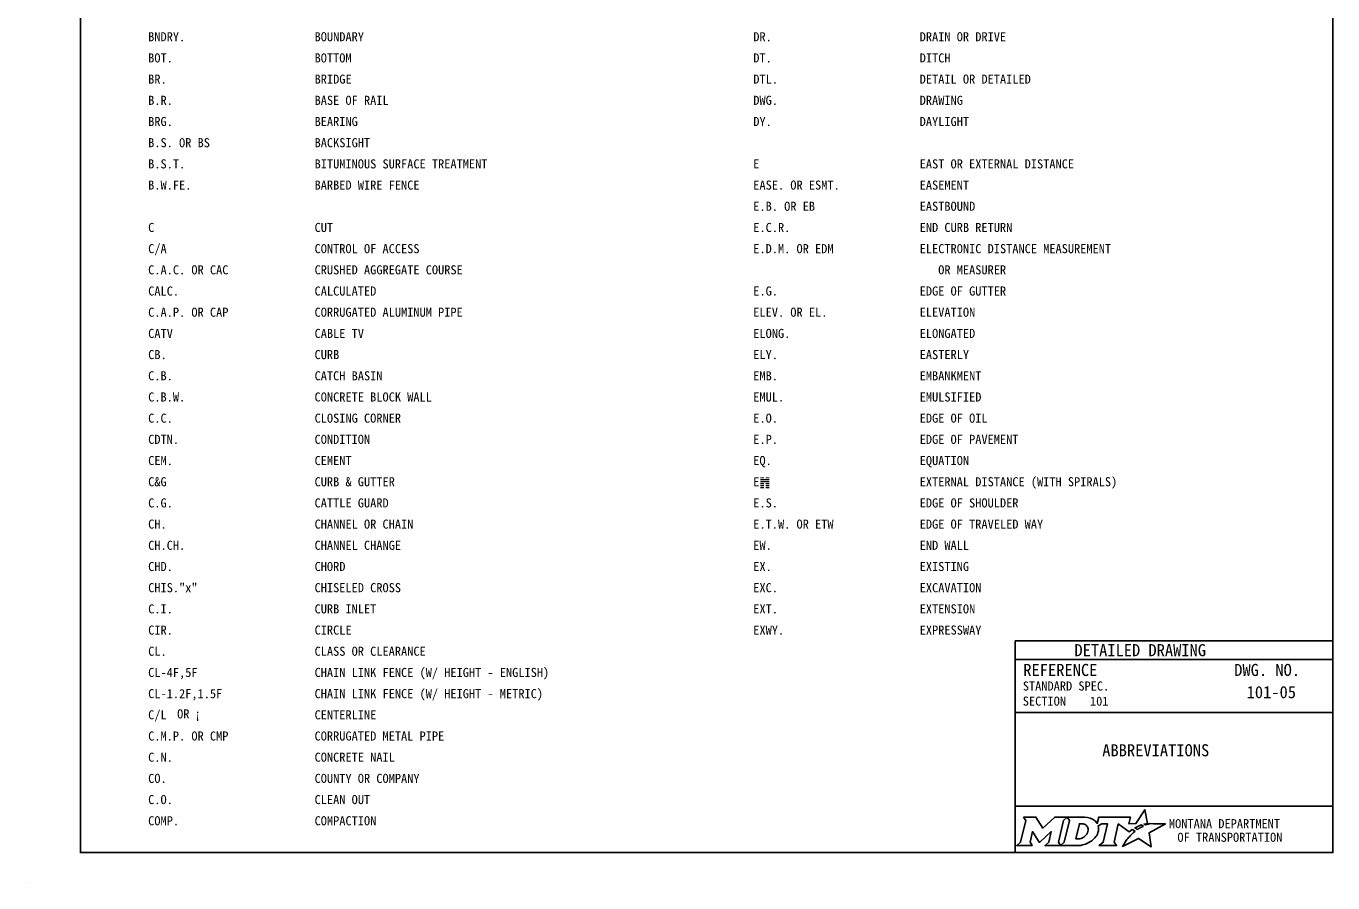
# Model space of a CAD drawing. Extents: x 49991.4 to 50021, y 49987.6 to 50011.4.
# Drawn here: x 49999.98 to 50008.61, y 49999.86 to 50005.52 of the extents above; entities that cross this region are included whole.
import ezdxf

# ---------------------------------------------------------------- set-up
doc = ezdxf.new("R2010")
doc.units = 0
for name, color, linetype in [('Default', 7, 'Continuous'), ('Level 1', 7, 'Continuous'), ('Level 2', 7, 'Continuous'), ('Level 5', 7, 'Continuous')]:
    doc.layers.add(name, color=color, linetype=linetype)

msp = doc.modelspace()

# ---------------------------------------------------------------- linework, layer by layer
at = {"layer": 'Level 1'}
msp.add_line((49999.9766, 49999.8624), (49999.9766, 49999.8624), dxfattribs=at)
msp.add_lwpolyline([(50008.6146, 50011.2628), (50000.3356, 50011.2628), (50000.3356, 50000.0624), (50008.6146, 50000.0624)], close=True, dxfattribs=at)
at = {"layer": 'Level 2'}
for p, q in [((50008.6146, 50001.4624), (50006.5146, 50001.4624)), ((50006.5146, 50001.4624), (50006.5146, 50000.0624)), ((50008.6146, 50001.3374), (50006.5146, 50001.3374)), ((50008.2507, 50001.1223), (50008.2507, 50001.1223)), ((50008.6146, 50000.9874), (50006.5146, 50000.9874)), ((50007.0089, 50001.0629), (50007.0089, 50001.0629)), ((50007.5646, 50000.7383), (50007.5646, 50000.7383)), ((50008.6146, 50000.3693), (50006.5146, 50000.3693))]:
    msp.add_line(p, q, dxfattribs=at)
for points in [[(50006.5701, 50000.2974), (50006.5842, 50000.274), (50006.5507, 50000.1307), (50006.525, 50000.1082), (50006.6266, 50000.1082), (50006.6131, 50000.131), (50006.6293, 50000.2011), (50006.673, 50000.1321), (50006.6783, 50000.1321), (50006.7534, 50000.2016), (50006.737, 50000.1305), (50006.7123, 50000.1085), (50006.8139, 50000.1085), (50006.8001, 50000.1318), (50006.8333, 50000.2742)], [(50006.8333, 50000.2742), (50006.8586, 50000.2974), (50006.7762, 50000.2974), (50006.6966, 50000.2244), (50006.6521, 50000.2971), (50006.5701, 50000.2974)], [(50006.9722, 50000.2974), (50006.8586, 50000.2974), (50006.8733, 50000.2745), (50006.8394, 50000.1307), (50006.8139, 50000.1085), (50006.9245, 50000.1085)], [(50007.3771, 50000.2447), (50007.3668, 50000.2503), (50007.3784, 50000.2531), (50007.39, 50000.2551), (50007.3726, 50000.3452), (50007.3131, 50000.2539), (50007.2658, 50000.2532), (50007.2761, 50000.2973), (50007.0669, 50000.2974), (50007.0568, 50000.2549), (50007.051, 50000.2632)], [(50006.9962, 50000.2107), (50006.995, 50000.2026), (50006.9918, 50000.1933), (50006.9876, 50000.1851), (50006.982, 50000.1776), (50006.9755, 50000.1707), (50006.9676, 50000.1644), (50006.9593, 50000.1597), (50006.9502, 50000.1558), (50006.9411, 50000.1535), (50006.9319, 50000.1526), (50006.916, 50000.1526), (50006.9396, 50000.2526), (50006.9556, 50000.2526), (50006.9632, 50000.252), (50006.9708, 50000.2501), (50006.9774, 50000.2471), (50006.9835, 50000.2429), (50006.9883, 50000.2379), (50006.992, 50000.2319), (50006.9947, 50000.2257), (50006.9963, 50000.2183), (50006.9963, 50000.2153), (50006.9962, 50000.2107)], [(50007.0636, 50000.2383), (50007.0882, 50000.2514), (50007.1251, 50000.2514), (50007.0965, 50000.1309), (50007.069, 50000.1082), (50007.1852, 50000.1082), (50007.1682, 50000.1311), (50007.1964, 50000.2513), (50007.2677, 50000.1996), (50007.2888, 50000.2147), (50007.3085, 50000.2038)], [(50007.2527, 50000.1479), (50007.2374, 50000.1235), (50007.2327, 50000.116), (50007.2269, 50000.1074), (50007.2246, 50000.1031), (50007.3299, 50000.1562), (50007.4138, 50000.1011), (50007.4007, 50000.1938), (50007.5076, 50000.2522), (50007.4583, 50000.253), (50007.4282, 50000.2534), (50007.4074, 50000.2537), (50007.4006, 50000.2522), (50007.3957, 50000.251), (50007.3873, 50000.2487), (50007.3771, 50000.2447)], [(50007.3267, 50000.2171), (50007.3243, 50000.2154), (50007.306, 50000.225), (50007.3163, 50000.2307), (50007.3204, 50000.2329), (50007.329, 50000.2369), (50007.3347, 50000.2395), (50007.3426, 50000.2425), (50007.3499, 50000.2452), (50007.3617, 50000.2378), (50007.3577, 50000.2357), (50007.3531, 50000.2332), (50007.3489, 50000.231), (50007.3439, 50000.2281), (50007.342, 50000.227), (50007.3393, 50000.2254), (50007.3368, 50000.224), (50007.3345, 50000.2224), (50007.3319, 50000.2206), (50007.3292, 50000.2188), (50007.3267, 50000.2171)], [(50006.9702, 50000.1158), (50006.9786, 50000.1184), (50006.9916, 50000.1238), (50007.012, 50000.1348)], [(50007.2666, 50000.164), (50007.2666, 50000.164)]]:
    msp.add_lwpolyline(points, dxfattribs=at)
for centre, radius, start, end in [((50006.9953, 50000.219), 0.0709, 339.53292, 15.85821), ((50006.9513, 50000.2363), 0.1183, 300.91025, 339.13831)]:
    msp.add_arc(centre, radius, start, end, dxfattribs=at)
for centre, major_axis, ratio, start_param, end_param in [((50006.9701, 50000.25), (0.0834, -0.0037), 0.568097, 0.61298, 1.570796), ((50007.0257, 50000.2573), (0.0361, -0.0295), 0.469099, 1.225588, 1.570796), ((50007.2974, 50000.1941), (-0.0112, -0.0097), 0.021651, 3.157348, 6.283185), ((50006.9248, 50000.2568), (0, 0.1484), 0.987302, 3.139398, 3.456847), ((50007.2597, 50000.1559), (-0.00694, -0.00806), 0.008222, 0, 3.137361), ((50007.2764, 50000.1742), (-0.0098, -0.0102), 0.016458, 3.141593, 6.279097)]:
    msp.add_ellipse(centre, major_axis=major_axis, ratio=ratio, start_param=start_param, end_param=end_param, dxfattribs=at)

# ---------------------------------------------------------------- texts
at = {"layer": 'Default'}
msp.add_text('OR ¡', height=0.06, dxfattribs=at).set_placement((50000.9747, 50000.9487))
at = {"layer": 'Level 2'}
for s, height, p in [('BNDRY.         ', 0.06, (50000.7833, 50005.4226)), ('BOUNDARY                                ', 0.06, (50001.8833, 50005.4226)), ('DR.            ', 0.06, (50004.7833, 50005.4226)), ('DRAIN OR DRIVE                          ', 0.06, (50005.8833, 50005.4226)), ('BOT.           ', 0.06, (50000.7833, 50005.2826)), ('BOTTOM                                  ', 0.06, (50001.8833, 50005.2826)), ('DT.            ', 0.06, (50004.7833, 50005.2826)), ('DITCH                                   ', 0.06, (50005.8833, 50005.2826)), ('BR.            ', 0.06, (50000.7833, 50005.1426)), ('BRIDGE                                  ', 0.06, (50001.8833, 50005.1426)), ('DTL.           ', 0.06, (50004.7833, 50005.1426)), ('DETAIL OR DETAILED                      ', 0.06, (50005.8833, 50005.1426)), ('B.R.           ', 0.06, (50000.7833, 50005.0026)), ('BASE OF RAIL                            ', 0.06, (50001.8833, 50005.0026)), ('DWG.           ', 0.06, (50004.7833, 50005.0026)), ('DRAWING                                 ', 0.06, (50005.8833, 50005.0026)), ('BRG.           ', 0.06, (50000.7833, 50004.8626)), ('BEARING                                 ', 0.06, (50001.8833, 50004.8626)), ('DY.            ', 0.06, (50004.7833, 50004.8626)), ('DAYLIGHT                                ', 0.06, (50005.8833, 50004.8626)), ('B.S. OR BS     ', 0.06, (50000.7833, 50004.7226)), ('BACKSIGHT                               ', 0.06, (50001.8833, 50004.7226)), ('B.S.T.         ', 0.06, (50000.7833, 50004.5826)), ('BITUMINOUS SURFACE TREATMENT            ', 0.06, (50001.8833, 50004.5826)), ('E              ', 0.06, (50004.7833, 50004.5826)), ('EAST OR EXTERNAL DISTANCE               ', 0.06, (50005.8833, 50004.5826)), ('B.W.FE.        ', 0.06, (50000.7833, 50004.4426)), ('BARBED WIRE FENCE                       ', 0.06, (50001.8833, 50004.4426)), ('EASE. OR ESMT. ', 0.06, (50004.7833, 50004.4426)), ('EASEMENT                                ', 0.06, (50005.8833, 50004.4426)), ('E.B. OR EB     ', 0.06, (50004.7833, 50004.3026)), ('EASTBOUND                               ', 0.06, (50005.8833, 50004.3026)), ('C              ', 0.06, (50000.7833, 50004.1626)), ('CUT                                     ', 0.06, (50001.8833, 50004.1626)), ('E.C.R.         ', 0.06, (50004.7833, 50004.1626)), ('END CURB RETURN                         ', 0.06, (50005.8833, 50004.1626)), ('C/A            ', 0.06, (50000.7833, 50004.0226)), ('CONTROL OF ACCESS                       ', 0.06, (50001.8833, 50004.0226)), ('E.D.M. OR EDM  ', 0.06, (50004.7833, 50004.0226)), ('ELECTRONIC DISTANCE MEASUREMENT         ', 0.06, (50005.8833, 50004.0226)), ('C.A.C. OR CAC  ', 0.06, (50000.7833, 50003.8826)), ('CRUSHED AGGREGATE COURSE                ', 0.06, (50001.8833, 50003.8826)), ('   OR MEASURER                          ', 0.06, (50005.8833, 50003.8826)), ('CALC.          ', 0.06, (50000.7833, 50003.7426)), ('CALCULATED                              ', 0.06, (50001.8833, 50003.7426)), ('E.G.           ', 0.06, (50004.7833, 50003.7426)), ('EDGE OF GUTTER                          ', 0.06, (50005.8833, 50003.7426)), ('C.A.P. OR CAP  ', 0.06, (50000.7833, 50003.6026)), ('CORRUGATED ALUMINUM PIPE                ', 0.06, (50001.8833, 50003.6026)), ('ELEV. OR EL.   ', 0.06, (50004.7833, 50003.6026)), ('ELEVATION                               ', 0.06, (50005.8833, 50003.6026)), ('CATV           ', 0.06, (50000.7833, 50003.4626)), ('CABLE TV                                ', 0.06, (50001.8833, 50003.4626)), ('ELONG.         ', 0.06, (50004.7833, 50003.4626)), ('ELONGATED                               ', 0.06, (50005.8833, 50003.4626)), ('CB.            ', 0.06, (50000.7833, 50003.3226)), ('CURB                                    ', 0.06, (50001.8833, 50003.3226)), ('ELY.           ', 0.06, (50004.7833, 50003.3226)), ('EASTERLY                                ', 0.06, (50005.8833, 50003.3226)), ('C.B.           ', 0.06, (50000.7833, 50003.1826)), ('CATCH BASIN                             ', 0.06, (50001.8833, 50003.1826)), ('EMB.           ', 0.06, (50004.7833, 50003.1826)), ('EMBANKMENT                              ', 0.06, (50005.8833, 50003.1826)), ('C.B.W.         ', 0.06, (50000.7833, 50003.0426)), ('CONCRETE BLOCK WALL                     ', 0.06, (50001.8833, 50003.0426)), ('EMUL.          ', 0.06, (50004.7833, 50003.0426)), ('EMULSIFIED                              ', 0.06, (50005.8833, 50003.0426)), ('C.C.           ', 0.06, (50000.7833, 50002.9026)), ('CLOSING CORNER                          ', 0.06, (50001.8833, 50002.9026)), ('E.O.           ', 0.06, (50004.7833, 50002.9026)), ('EDGE OF OIL                             ', 0.06, (50005.8833, 50002.9026)), ('CDTN.          ', 0.06, (50000.7833, 50002.7626)), ('CONDITION                               ', 0.06, (50001.8833, 50002.7626)), ('E.P.           ', 0.06, (50004.7833, 50002.7626)), ('EDGE OF PAVEMENT                        ', 0.06, (50005.8833, 50002.7626)), ('CEM.           ', 0.06, (50000.7833, 50002.6226)), ('CEMENT                                  ', 0.06, (50001.8833, 50002.6226)), ('EQ.            ', 0.06, (50004.7833, 50002.6226)), ('EQUATION                                ', 0.06, (50005.8833, 50002.6226)), ('C&G            ', 0.06, (50000.7833, 50002.4826)), ('CURB & GUTTER                           ', 0.06, (50001.8833, 50002.4826)), ('E䷬', 0.06, (50004.7833, 50002.4826)), ('EXTERNAL DISTANCE (WITH SPIRALS)        ', 0.06, (50005.8833, 50002.4826)), ('C.G.            ', 0.06, (50000.7833, 50002.3426)), ('CATTLE GUARD                        ', 0.06, (50001.8833, 50002.3426)), ('E.S.           ', 0.06, (50004.7833, 50002.3426)), ('EDGE OF SHOULDER                        ', 0.06, (50005.8833, 50002.3426)), ('CH.            ', 0.06, (50000.7833, 50002.2026)), ('CHANNEL OR CHAIN                        ', 0.06, (50001.8833, 50002.2026)), ('E.T.W. OR ETW  ', 0.06, (50004.7833, 50002.2026)), ('EDGE OF TRAVELED WAY                    ', 0.06, (50005.8833, 50002.2026)), ('CH.CH.         ', 0.06, (50000.7833, 50002.0626)), ('CHANNEL CHANGE                          ', 0.06, (50001.8833, 50002.0626)), ('EW.            ', 0.06, (50004.7833, 50002.0626)), ('END WALL                                ', 0.06, (50005.8833, 50002.0626)), ('CHD.           ', 0.06, (50000.7833, 50001.9226)), ('CHORD                                   ', 0.06, (50001.8833, 50001.9226)), ('EX.            ', 0.06, (50004.7833, 50001.9226)), ('EXISTING                                ', 0.06, (50005.8833, 50001.9226)), ('CHIS."x"       ', 0.06, (50000.7833, 50001.7826)), ('CHISELED CROSS                          ', 0.06, (50001.8833, 50001.7826)), ('EXC.           ', 0.06, (50004.7833, 50001.7826)), ('EXCAVATION                              ', 0.06, (50005.8833, 50001.7826)), ('C.I.           ', 0.06, (50000.7833, 50001.6426)), ('CURB INLET                              ', 0.06, (50001.8833, 50001.6426)), ('EXT.           ', 0.06, (50004.7833, 50001.6426)), ('EXTENSION                               ', 0.06, (50005.8833, 50001.6426)), ('CIR.           ', 0.06, (50000.7833, 50001.5026)), ('CIRCLE                                  ', 0.06, (50001.8833, 50001.5026)), ('EXWY.          ', 0.06, (50004.7833, 50001.5026)), ('EXPRESSWAY                              ', 0.06, (50005.8833, 50001.5026)), ('CL.            ', 0.06, (50000.7833, 50001.3626)), ('CLASS OR CLEARANCE                      ', 0.06, (50001.8833, 50001.3626)), ('CL-4F,5F       ', 0.06, (50000.7833, 50001.2226)), ('CHAIN LINK FENCE (W/ HEIGHT - ENGLISH)  ', 0.06, (50001.8833, 50001.2226)), ('REFERENCE', 0.08, (50006.5682, 50001.229)), ('DWG. NO.', 0.08, (50007.9624, 50001.229)), ('STANDARD SPEC.', 0.06, (50006.5649, 50001.133)), ('101-05', 0.08, (50008.0444, 50001.0823)), ('CL-1.2F,1.5F   ', 0.06, (50000.7833, 50001.0826)), ('CHAIN LINK FENCE (W/ HEIGHT - METRIC)   ', 0.06, (50001.8833, 50001.0826)), ('SECTION', 0.06, (50006.5649, 50001.033)), ('101', 0.06, (50007.0089, 50001.0329)), ('C/L            ', 0.06, (50000.7833, 50000.9426)), ('CENTERLINE                              ', 0.06, (50001.8833, 50000.9426)), ('C.M.P. OR CMP  ', 0.06, (50000.7833, 50000.8026)), ('CORRUGATED METAL PIPE                   ', 0.06, (50001.8833, 50000.8026)), ('C.N.           ', 0.06, (50000.7833, 50000.6626)), ('CONCRETE NAIL                           ', 0.06, (50001.8833, 50000.6626)), ('ABBREVIATIONS', 0.08, (50007.09, 50000.6983)), ('CO.            ', 0.06, (50000.7833, 50000.5226)), ('COUNTY OR COMPANY                       ', 0.06, (50001.8833, 50000.5226)), ('C.O.           ', 0.06, (50000.7833, 50000.3826)), ('CLEAN OUT                               ', 0.06, (50001.8833, 50000.3826)), ('COMP.          ', 0.06, (50000.7833, 50000.2426)), ('COMPACTION                              ', 0.06, (50001.8833, 50000.2426)), ('MONTANA DEPARTMENT', 0.06, (50007.5308, 50000.2236)), ('OF TRANSPORTATION', 0.06, (50007.587, 50000.1336))]:
    msp.add_text(s, height=height, dxfattribs=at).set_placement(p)
at = {"layer": 'Level 5'}
msp.add_text('DETAILED DRAWING', height=0.0799, dxfattribs=at).set_placement((50006.9063, 50001.3599))

doc.saveas('drawing.dxf')
